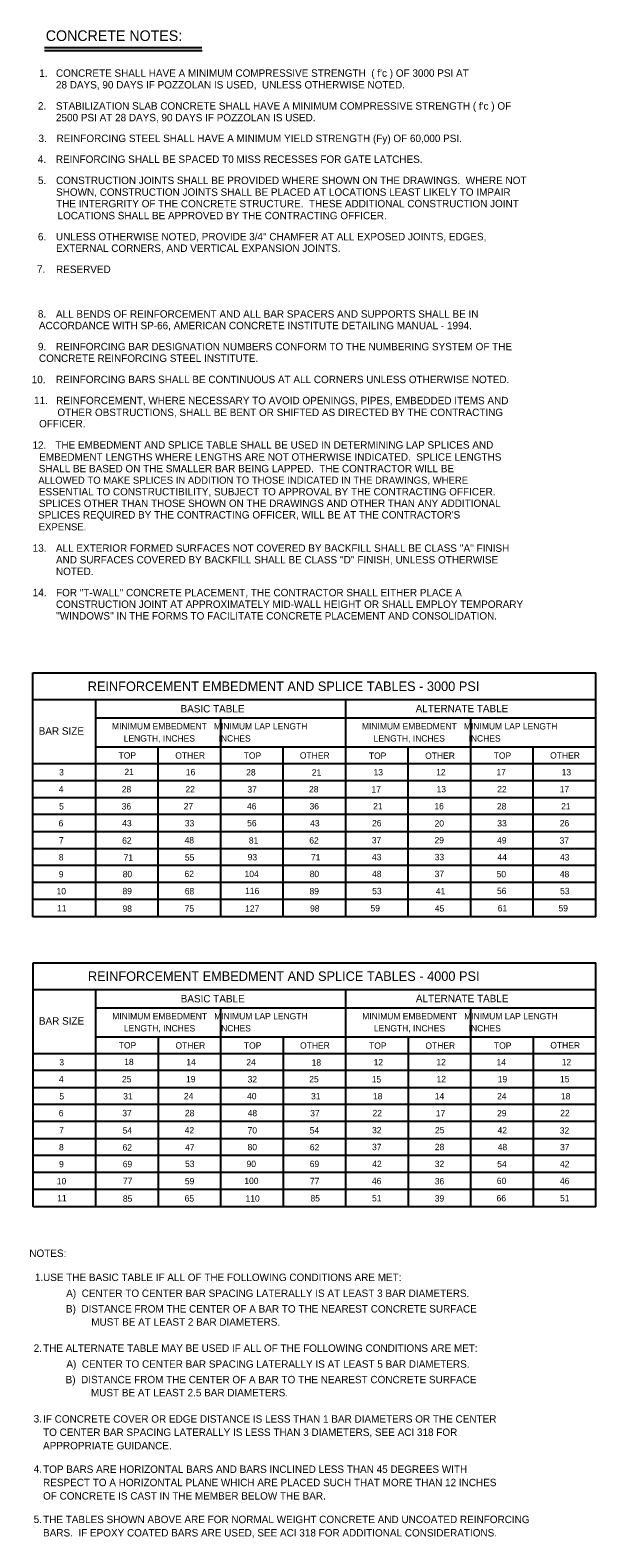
# Model space of a CAD drawing. Extents: x 22369.62 to 22376.4, y 22369.62 to 22372.46.
# Drawn here: x 22373.565 to 22374.455, y 22369.771 to 22372.143 of the extents above; entities that cross this region are included whole.
import ezdxf

# ---------------------------------------------------------------- set-up
doc = ezdxf.new("R2010")
doc.units = 0
for name, color, linetype in [('Level 1', 7, 'Continuous'), ('Level 10', 7, 'Continuous'), ('Level 2', 7, 'Continuous'), ('Level 3', 7, 'Continuous'), ('Level 4', 7, 'Continuous'), ('Level 7', 7, 'Continuous')]:
    doc.layers.add(name, color=color, linetype=linetype)

msp = doc.modelspace()

# ---------------------------------------------------------------- linework, layer by layer
at = {"layer": 'Level 1'}
for p, q in [((22374.4551, 22370.9623), (22373.5694, 22370.9623)), ((22374.4551, 22370.9355), (22373.5694, 22370.9355)), ((22374.4551, 22370.9089), (22373.5694, 22370.9089)), ((22374.4551, 22370.882), (22373.5694, 22370.882)), ((22374.4551, 22370.8552), (22373.5694, 22370.8552)), ((22374.4551, 22370.8288), (22373.5694, 22370.8288)), ((22374.4551, 22370.8021), (22373.5694, 22370.8021)), ((22374.4551, 22370.7753), (22373.5694, 22370.7753)), ((22374.4554, 22370.5061), (22373.5698, 22370.5061)), ((22374.4554, 22370.4793), (22373.5698, 22370.4793)), ((22374.4554, 22370.4527), (22373.5698, 22370.4527)), ((22374.4554, 22370.4259), (22373.5698, 22370.4259)), ((22374.4554, 22370.399), (22373.5698, 22370.399)), ((22374.4554, 22370.3726), (22373.5698, 22370.3726)), ((22374.4554, 22370.346), (22373.5698, 22370.346)), ((22374.4554, 22370.3191), (22373.5698, 22370.3191))]:
    msp.add_line(p, q, dxfattribs=at)
at = {"layer": 'Level 10'}
for p, q in [((22373.5878, 22372.1161), (22373.8351, 22372.1161)), ((22373.5878, 22372.1111), (22373.8358, 22372.1111)), ((22373.5694, 22370.7479), (22373.5694, 22371.1318)), ((22373.5694, 22371.1318), (22374.4551, 22371.1318)), ((22374.4551, 22370.7479), (22374.4551, 22371.1318)), ((22373.5694, 22371.09), (22374.4551, 22371.09)), ((22374.4551, 22370.7479), (22373.5694, 22370.7479)), ((22373.5698, 22370.2917), (22373.5698, 22370.6756)), ((22373.5698, 22370.6756), (22374.4554, 22370.6756)), ((22374.4554, 22370.2917), (22374.4554, 22370.6756)), ((22373.5698, 22370.6338), (22374.4554, 22370.6338)), ((22374.4554, 22370.2917), (22373.5698, 22370.2917))]:
    msp.add_line(p, q, dxfattribs=at)
at = {"layer": 'Level 2'}
for p, q in [((22373.6682, 22371.0156), (22374.4551, 22371.0156)), ((22373.7666, 22370.7479), (22373.7666, 22371.0156)), ((22373.9633, 22370.7479), (22373.9633, 22371.0156)), ((22374.16, 22370.7479), (22374.16, 22371.0156)), ((22374.3567, 22370.7479), (22374.3567, 22371.0156)), ((22373.7669, 22370.2917), (22373.7669, 22370.5594)), ((22373.9636, 22370.2917), (22373.9636, 22370.5594)), ((22374.1604, 22370.2917), (22374.1604, 22370.5594)), ((22374.357, 22370.2917), (22374.357, 22370.5594))]:
    msp.add_line(p, q, dxfattribs=at)
at = {"layer": 'Level 7'}
for p, q in [((22373.6682, 22370.7479), (22373.6682, 22371.09)), ((22374.0617, 22370.7479), (22374.0617, 22371.09)), ((22373.6682, 22371.0613), (22374.4551, 22371.0613)), ((22373.8649, 22370.7479), (22373.8649, 22371.0613)), ((22374.2584, 22370.7479), (22374.2584, 22371.0613)), ((22374.4551, 22370.9889), (22373.5694, 22370.9889)), ((22373.6685, 22370.2917), (22373.6685, 22370.6338)), ((22374.062, 22370.2917), (22374.062, 22370.6338)), ((22373.6685, 22370.6051), (22374.4554, 22370.6051)), ((22373.8653, 22370.2917), (22373.8653, 22370.6051)), ((22374.2587, 22370.2917), (22374.2587, 22370.6051)), ((22373.6685, 22370.5594), (22374.4554, 22370.5594)), ((22374.4554, 22370.5327), (22373.5698, 22370.5327))]:
    msp.add_line(p, q, dxfattribs=at)

# ---------------------------------------------------------------- texts
at = {"layer": 'Level 3'}
msp.add_text('CONCRETE NOTES:', height=0.016698, dxfattribs=at).set_placement((22373.5896, 22372.1262))
at = {"layer": 'Level 4'}
for s, height, p in [('1.', 0.0117, (22373.5794, 22372.0697)), ("CONCRETE SHALL HAVE A MINIMUM COMPRESSIVE STRENGTH  ( f'c ) OF 3000 PSI AT", 0.011698, (22373.6056, 22372.0698)), ('28 DAYS, 90 DAYS IF POZZOLAN IS USED,  UNLESS OTHERWISE NOTED.', 0.011698, (22373.6056, 22372.0514)), ('2.', 0.0117, (22373.5772, 22372.0182)), ("STABILIZATION SLAB CONCRETE SHALL HAVE A MINIMUM COMPRESSIVE STRENGTH ( f'c ) OF", 0.011698, (22373.6055, 22372.0181)), ('2500 PSI AT 28 DAYS, 90 DAYS IF POZZOLAN IS USED.', 0.011698, (22373.6056, 22371.9998)), ('3.', 0.0117, (22373.5781, 22371.9671)), ('REINFORCING STEEL SHALL HAVE A MINIMUM YIELD STRENGTH (Fy) OF 60,000 PSI.', 0.011698, (22373.6065, 22371.9671)), ('4.', 0.0117, (22373.5771, 22371.9344)), ('REINFORCING SHALL BE SPACED T0 MISS RECESSES FOR GATE LATCHES.', 0.011698, (22373.6054, 22371.9343)), ('5.', 0.0117, (22373.5773, 22371.901)), ('CONSTRUCTION JOINTS SHALL BE PROVIDED WHERE SHOWN ON THE DRAWINGS.  WHERE NOT', 0.011698, (22373.6057, 22371.901)), ('SHOWN, CONSTRUCTION JOINTS SHALL BE PLACED AT LOCATIONS LEAST LIKELY TO IMPAIR', 0.011698, (22373.6058, 22371.8826)), ('THE INTERGRITY OF THE CONCRETE STRUCTURE.  THESE ADDITIONAL CONSTRUCTION JOINT', 0.011698, (22373.6058, 22371.8644)), ('LOCATIONS SHALL BE APPROVED BY THE CONTRACTING OFFICER.', 0.011698, (22373.6081, 22371.8456)), ('6.', 0.0117, (22373.5772, 22371.8125)), ('UNLESS OTHERWISE NOTED, PROVIDE 3/4" CHAMFER AT ALL EXPOSED JOINTS, EDGES,', 0.011698, (22373.6056, 22371.8125)), ('EXTERNAL CORNERS, AND VERTICAL EXPANSION JOINTS.', 0.011698, (22373.6057, 22371.7943)), ('7.', 0.0117, (22373.5757, 22371.7615)), ('RESERVED', 0.0117, (22373.6057, 22371.7611)), ('8.', 0.0117, (22373.5772, 22371.6909)), ('ALL BENDS OF REINFORCEMENT AND ALL BAR SPACERS AND SUPPORTS SHALL BE IN', 0.011698, (22373.6056, 22371.6908)), ('    ACCORDANCE WITH SP-66, AMERICAN CONCRETE INSTITUTE DETAILING MANUAL - 1994.', 0.011698, (22373.5614, 22371.6726)), ('9.', 0.0117, (22373.5772, 22371.6395)), ('REINFORCING BAR DESIGNATION NUMBERS CONFORM TO THE NUMBERING SYSTEM OF THE', 0.011698, (22373.6056, 22371.6395)), ('    CONCRETE REINFORCING STEEL INSTITUTE.', 0.011698, (22373.5614, 22371.6212)), ('10.', 0.0117, (22373.5674, 22371.5877)), ('REINFORCING BARS SHALL BE CONTINUOUS AT ALL CORNERS UNLESS OTHERWISE NOTED.', 0.011698, (22373.6056, 22371.5878)), ('11.', 0.0117, (22373.5711, 22371.5549)), ('REINFORCEMENT, WHERE NECESSARY TO AVOID OPENINGS, PIPES, EMBEDDED ITEMS AND', 0.011698, (22373.6059, 22371.5546)), ('    OFFICER.', 0.011698, (22373.5616, 22371.5182)), ('OTHER OBSTRUCTIONS, SHALL BE BENT OR SHIFTED AS DIRECTED BY THE CONTRACTING', 0.011698, (22373.6079, 22371.536)), ('12.', 0.0117, (22373.5686, 22371.4845)), ('THE EMBEDMENT AND SPLICE TABLE SHALL BE USED IN DETERMINING LAP SPLICES AND', 0.011698, (22373.6046, 22371.4848)), ('    SHALL BE BASED ON THE SMALLER BAR BEING LAPPED.  THE CONTRACTOR WILL BE', 0.011698, (22373.5611, 22371.4475)), ('    EMBEDMENT LENGTHS WHERE LENGTHS ARE NOT OTHERWISE INDICATED.  SPLICE LENGTHS', 0.011698, (22373.5618, 22371.4658)), ('    ALLOWED TO MAKE SPLICES IN ADDITION TO THOSE INDICATED IN THE DRAWINGS, WHERE', 0.0112, (22373.5611, 22371.4295)), ('    ESSENTIAL TO CONSTRUCTIBILITY, SUBJECT TO APPROVAL BY THE CONTRACTING OFFICER.', 0.011698, (22373.5614, 22371.4112)), ('    SPLICES OTHER THAN THOSE SHOWN ON THE DRAWINGS AND OTHER THAN ANY ADDITIONAL', 0.011698, (22373.5614, 22371.3929)), ("    SPLICES REQUIRED BY THE CONTRACTING OFFICER, WILL BE AT THE CONTRACTOR'S", 0.011698, (22373.5601, 22371.3748)), ('    EXPENSE.', 0.0112, (22373.5618, 22371.3561)), ('13.', 0.0117, (22373.569, 22371.3225)), ("ALL EXTERIOR FORMED SURFACES NOT COVERED BY BACKFILL SHALL BE CLASS ''A'' FINISH", 0.011698, (22373.6056, 22371.3224)), ("AND SURFACES COVERED BY BACKFILL SHALL BE CLASS ''D'' FINISH, UNLESS OTHERWISE", 0.011698, (22373.6056, 22371.3041)), ('NOTED.', 0.0117, (22373.6056, 22371.2858)), ('14.', 0.0117, (22373.569, 22371.2525)), ('CONSTRUCTION JOINT AT APPROXIMATELY MID-WALL HEIGHT OR SHALL EMPLOY TEMPORARY', 0.011698, (22373.6056, 22371.2342)), ('FOR "T-WALL" CONCRETE PLACEMENT, THE CONTRACTOR SHALL EITHER PLACE A', 0.011698, (22373.6057, 22371.2524)), ("''WINDOWS'' IN THE FORMS TO FACILITATE CONCRETE PLACEMENT AND CONSOLIDATION.", 0.011698, (22373.6056, 22371.2158)), ('REINFORCEMENT EMBEDMENT AND SPLICE TABLES - 3000 PSI', 0.015, (22373.6556, 22371.1034)), ('BASIC TABLE', 0.011667, (22373.8017, 22371.0697)), ('ALTERNATE TABLE', 0.011667, (22374.1718, 22371.07)), ('BAR SIZE', 0.0117, (22373.5784, 22371.0347)), ('MINIMUM EMBEDMENT   MINIMUM LAP LENGTH', 0.01, (22373.6938, 22371.0429)), ('LENGTH, INCHES          INCHES', 0.01, (22373.7122, 22371.0239)), ('MINIMUM EMBEDMENT   MINIMUM LAP LENGTH', 0.01, (22374.0872, 22371.0429)), ('LENGTH, INCHES          INCHES', 0.01, (22374.1056, 22371.0239)), ('TOP', 0.01, (22373.7041, 22370.9971)), ('OTHER', 0.01, (22373.7934, 22370.997)), ('TOP', 0.01, (22373.9011, 22370.9969)), ('OTHER', 0.01, (22373.9895, 22370.997)), ('TOP', 0.01, (22374.0981, 22370.9967)), ('OTHER', 0.01, (22374.1867, 22370.9967)), ('TOP', 0.01, (22374.2946, 22370.9968)), ('OTHER', 0.01, (22374.3834, 22370.9972)), ('3', 0.01, (22373.6105, 22370.9706)), ('21', 0.01, (22373.7133, 22370.9711)), ('16', 0.01, (22373.81, 22370.9709)), ('28', 0.01, (22373.905, 22370.9705)), ('21', 0.01, (22374.0083, 22370.9703)), ('13', 0.01, (22374.1055, 22370.9706)), ('12', 0.01, (22374.2041, 22370.9708)), ('17', 0.01, (22374.2988, 22370.9706)), ('13', 0.01, (22374.4015, 22370.9708)), ('4', 0.01, (22373.6099, 22370.9438)), ('28', 0.01, (22373.7092, 22370.9439)), ('22', 0.01, (22373.8094, 22370.9439)), ('37', 0.01, (22373.9069, 22370.9437)), ('28', 0.01, (22374.0039, 22370.9439)), ('17', 0.01, (22374.1022, 22370.9437)), ('13', 0.01, (22374.2046, 22370.9441)), ('22', 0.01, (22374.3001, 22370.9439)), ('17', 0.01, (22374.3986, 22370.9441)), ('5', 0.01, (22373.6106, 22370.917)), ('36', 0.01, (22373.709, 22370.917)), ('27', 0.01, (22373.8067, 22370.9172)), ('46', 0.01, (22373.9063, 22370.9171)), ('36', 0.01, (22374.0047, 22370.9171)), ('21', 0.01, (22374.1048, 22370.9172)), ('16', 0.01, (22374.2012, 22370.9172)), ('28', 0.01, (22374.2997, 22370.917)), ('21', 0.01, (22374.4007, 22370.917)), ('6', 0.01, (22373.6097, 22370.8904)), ('43', 0.01, (22373.7099, 22370.8905)), ('33', 0.01, (22373.8084, 22370.8905)), ('56', 0.01, (22373.9065, 22370.8905)), ('43', 0.01, (22374.0057, 22370.8904)), ('26', 0.01, (22374.1031, 22370.8906)), ('20', 0.01, (22374.2015, 22370.8902)), ('33', 0.01, (22374.3002, 22370.8904)), ('26', 0.01, (22374.3986, 22370.8905)), ('7', 0.01, (22373.6103, 22370.8635)), ('62', 0.01, (22373.7098, 22370.8633)), ('48', 0.01, (22373.808, 22370.8636)), ('81', 0.01, (22373.9092, 22370.8634)), ('62', 0.01, (22374.0043, 22370.8634)), ('37', 0.01, (22374.1027, 22370.8637)), ('29', 0.01, (22374.2014, 22370.8637)), ('49', 0.01, (22374.2999, 22370.8635)), ('37', 0.01, (22374.3983, 22370.8633)), ('8', 0.01, (22373.6101, 22370.8369)), ('71', 0.01, (22373.7121, 22370.8366)), ('55', 0.01, (22373.8085, 22370.8366)), ('93', 0.01, (22373.9073, 22370.837)), ('71', 0.01, (22374.0069, 22370.8368)), ('43', 0.01, (22374.1029, 22370.8372)), ('33', 0.01, (22374.2017, 22370.8372)), ('44', 0.01, (22374.3005, 22370.837)), ('43', 0.01, (22374.3989, 22370.8368)), ('9', 0.01, (22373.6101, 22370.8103)), ('80', 0.01, (22373.7106, 22370.8104)), ('62', 0.01, (22373.8079, 22370.8107)), ('104', 0.01, (22373.9024, 22370.8106)), ('80', 0.01, (22374.0049, 22370.8106)), ('48', 0.01, (22374.1031, 22370.8106)), ('37', 0.01, (22374.2015, 22370.8106)), ('50', 0.01, (22374.2992, 22370.8104)), ('48', 0.01, (22374.3987, 22370.8104)), ('10', 0.01, (22373.6065, 22370.7835)), ('89', 0.01, (22373.7103, 22370.7837)), ('68', 0.01, (22373.8083, 22370.7835)), ('116', 0.01, (22373.9033, 22370.7838)), ('89', 0.01, (22374.0047, 22370.7836)), ('53', 0.01, (22374.1033, 22370.7837)), ('41', 0.01, (22374.2035, 22370.7835)), ('56', 0.01, (22374.2997, 22370.7839)), ('53', 0.01, (22374.3991, 22370.7837)), ('11', 0.01, (22373.6073, 22370.7566)), ('98', 0.01, (22373.7103, 22370.756)), ('75', 0.01, (22373.8082, 22370.7563)), ('127', 0.01, (22373.9034, 22370.7562)), ('98', 0.01, (22374.0055, 22370.7564)), ('59', 0.01, (22374.1007, 22370.7566)), ('45', 0.01, (22374.2019, 22370.7564)), ('61', 0.01, (22374.3009, 22370.7566)), ('59', 0.01, (22374.3966, 22370.7566)), ('REINFORCEMENT EMBEDMENT AND SPLICE TABLES - 4000 PSI', 0.015, (22373.6559, 22370.6473)), ('BASIC TABLE', 0.011667, (22373.802, 22370.6135)), ('ALTERNATE TABLE', 0.011667, (22374.1721, 22370.6138)), ('BAR SIZE', 0.0117, (22373.5787, 22370.5785)), ('MINIMUM EMBEDMENT   MINIMUM LAP LENGTH', 0.01, (22373.6941, 22370.5867)), ('MINIMUM EMBEDMENT   MINIMUM LAP LENGTH', 0.01, (22374.0876, 22370.5867)), ('LENGTH, INCHES          INCHES', 0.01, (22373.7125, 22370.5678)), ('LENGTH, INCHES          INCHES', 0.01, (22374.1059, 22370.5678)), ('TOP', 0.01, (22373.7044, 22370.541)), ('OTHER', 0.01, (22373.7937, 22370.5408)), ('TOP', 0.01, (22373.9014, 22370.5407)), ('OTHER', 0.01, (22373.9898, 22370.5408)), ('TOP', 0.01, (22374.0984, 22370.5405)), ('OTHER', 0.01, (22374.1871, 22370.5405)), ('TOP', 0.01, (22374.295, 22370.5406)), ('OTHER', 0.01, (22374.3837, 22370.541)), ('3', 0.01, (22373.6109, 22370.5144)), ('18', 0.01, (22373.713, 22370.515)), ('14', 0.01, (22373.8108, 22370.5147)), ('24', 0.01, (22373.9052, 22370.5143)), ('18', 0.01, (22374.008, 22370.5141)), ('12', 0.01, (22374.1056, 22370.5144)), ('12', 0.01, (22374.2044, 22370.5146)), ('14', 0.01, (22374.2991, 22370.5144)), ('12', 0.01, (22374.4016, 22370.5146)), ('4', 0.01, (22373.6102, 22370.4876)), ('25', 0.01, (22373.7095, 22370.4877)), ('19', 0.01, (22373.8103, 22370.4877)), ('32', 0.01, (22373.9072, 22370.4875)), ('25', 0.01, (22374.0042, 22370.4877)), ('15', 0.01, (22374.1026, 22370.4875)), ('12', 0.01, (22374.2047, 22370.4879)), ('19', 0.01, (22374.3009, 22370.4877)), ('15', 0.01, (22374.3989, 22370.4879)), ('5', 0.01, (22373.611, 22370.4608)), ('31', 0.01, (22373.7114, 22370.4608)), ('24', 0.01, (22373.807, 22370.4611)), ('40', 0.01, (22373.9064, 22370.461)), ('31', 0.01, (22374.0071, 22370.461)), ('18', 0.01, (22374.1045, 22370.461)), ('14', 0.01, (22374.2019, 22370.461)), ('24', 0.01, (22374.2999, 22370.4609)), ('18', 0.01, (22374.4004, 22370.4609)), ('6', 0.01, (22373.61, 22370.4342)), ('37', 0.01, (22373.71, 22370.4344)), ('28', 0.01, (22373.8086, 22370.4344)), ('48', 0.01, (22373.9073, 22370.4344)), ('37', 0.01, (22374.0058, 22370.4342)), ('22', 0.01, (22374.1039, 22370.4344)), ('17', 0.01, (22374.2034, 22370.434)), ('29', 0.01, (22374.2999, 22370.4342)), ('22', 0.01, (22374.3993, 22370.4344)), ('7', 0.01, (22373.6106, 22370.4074)), ('54', 0.01, (22373.7105, 22370.4071)), ('42', 0.01, (22373.8082, 22370.4074)), ('70', 0.01, (22373.9072, 22370.4072)), ('54', 0.01, (22374.005, 22370.4072)), ('32', 0.01, (22374.1031, 22370.4075)), ('25', 0.01, (22374.2022, 22370.4075)), ('42', 0.01, (22374.3006, 22370.4073)), ('32', 0.01, (22374.3986, 22370.4071)), ('8', 0.01, (22373.6104, 22370.3807)), ('80', 0.01, (22373.9072, 22370.3808)), ('37', 0.01, (22374.1031, 22370.381)), ('28', 0.01, (22374.2019, 22370.381)), ('48', 0.01, (22374.3009, 22370.3809)), ('37', 0.01, (22374.399, 22370.3807)), ('62', 0.01, (22373.7104, 22370.3804)), ('47', 0.01, (22373.8088, 22370.3804)), ('62', 0.01, (22374.0052, 22370.3806)), ('9', 0.01, (22373.6104, 22370.3541)), ('69', 0.01, (22373.7107, 22370.3542)), ('53', 0.01, (22373.8088, 22370.3545)), ('90', 0.01, (22373.9056, 22370.3544)), ('69', 0.01, (22374.005, 22370.3544)), ('42', 0.01, (22374.1034, 22370.3545)), ('32', 0.01, (22374.2018, 22370.3545)), ('54', 0.01, (22374.3001, 22370.3542)), ('42', 0.01, (22374.3989, 22370.3542)), ('10', 0.01, (22373.6069, 22370.3273)), ('77', 0.01, (22373.711, 22370.3276)), ('59', 0.01, (22373.8085, 22370.3273)), ('100', 0.01, (22373.9021, 22370.3277)), ('77', 0.01, (22374.0054, 22370.3275)), ('46', 0.01, (22374.1029, 22370.3275)), ('36', 0.01, (22374.2018, 22370.3273)), ('60', 0.01, (22374.2995, 22370.3277)), ('46', 0.01, (22374.3988, 22370.3275)), ('11', 0.01, (22373.6076, 22370.3005)), ('85', 0.01, (22373.7109, 22370.2998)), ('65', 0.01, (22373.8081, 22370.3001)), ('110', 0.01, (22373.904, 22370.3001)), ('85', 0.01, (22374.0062, 22370.3003)), ('51', 0.01, (22374.1031, 22370.3004)), ('39', 0.01, (22374.2018, 22370.3002)), ('66', 0.01, (22374.2991, 22370.3005)), ('51', 0.01, (22374.399, 22370.3005)), ('NOTES:', 0.0117, (22373.5637, 22370.213)), ('1.', 0.0117, (22373.5725, 22370.1752)), ('  USE THE BASIC TABLE IF ALL OF THE FOLLOWING CONDITIONS ARE MET:', 0.011698, (22373.5766, 22370.1751)), ('A)  CENTER TO CENTER BAR SPACING LATERALLY IS AT LEAST 3 BAR DIAMETERS.', 0.011698, (22373.6217, 22370.15)), ('B)  DISTANCE FROM THE CENTER OF A BAR TO THE NEAREST CONCRETE SURFACE', 0.011698, (22373.6213, 22370.1255)), ('MUST BE AT LEAST 2 BAR DIAMETERS.', 0.011698, (22373.6611, 22370.1049)), ('2.', 0.0117, (22373.5705, 22370.0637)), ('  THE ALTERNATE TABLE MAY BE USED IF ALL OF THE FOLLOWING CONDITIONS ARE MET:', 0.011698, (22373.5766, 22370.0637)), ('A)  CENTER TO CENTER BAR SPACING LATERALLY IS AT LEAST 5 BAR DIAMETERS.', 0.011698, (22373.622, 22370.0387)), ('B)  DISTANCE FROM THE CENTER OF A BAR TO THE NEAREST CONCRETE SURFACE', 0.011698, (22373.6208, 22370.0142)), ('MUST BE AT LEAST 2.5 BAR DIAMETERS.', 0.011698, (22373.6606, 22369.9937)), ('3.', 0.0117, (22373.5705, 22369.9526)), ('  IF CONCRETE COVER OR EDGE DISTANCE IS LESS THAN 1 BAR DIAMETERS OR THE CENTER', 0.011698, (22373.5766, 22369.9523)), ('  TO CENTER BAR SPACING LATERALLY IS LESS THAN 3 DIAMETERS, SEE ACI 318 FOR', 0.011698, (22373.5766, 22369.9314)), ('  APPROPRIATE GUIDANCE.', 0.011698, (22373.5766, 22369.9103)), ('4.', 0.0117, (22373.5705, 22369.8735)), ('  TOP BARS ARE HORIZONTAL BARS AND BARS INCLINED LESS THAN 45 DEGREES WITH', 0.011698, (22373.5766, 22369.8732)), ('  RESPECT TO A HORIZONTAL PLANE WHICH ARE PLACED SUCH THAT MORE THAN 12 INCHES', 0.011698, (22373.5766, 22369.8523)), ('  OF CONCRETE IS CAST IN THE MEMBER BELOW THE BAR.', 0.011698, (22373.5766, 22369.8312)), ('5.', 0.0117, (22373.5705, 22369.7944)), ('  THE TABLES SHOWN ABOVE ARE FOR NORMAL WEIGHT CONCRETE AND UNCOATED REINFORCING', 0.011698, (22373.5766, 22369.7942)), ('  BARS.  IF EPOXY COATED BARS ARE USED, SEE ACI 318 FOR ADDITIONAL CONSIDERATIONS.', 0.011698, (22373.5766, 22369.7732))]:
    msp.add_text(s, height=height, dxfattribs=at).set_placement(p)

doc.saveas('drawing.dxf')
